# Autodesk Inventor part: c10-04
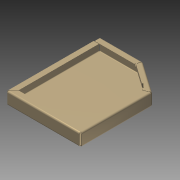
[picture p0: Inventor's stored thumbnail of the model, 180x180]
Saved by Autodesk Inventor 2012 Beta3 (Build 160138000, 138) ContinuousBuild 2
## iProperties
Created: 2011-01
Part Number: c10-04
Material: Aluminum-6061
Document SubType Name: Sheet Metal
Designer: Beta-8540w
Density: 2.71 g/cm^3
Sheet Metal Rule: Aluminum 3 mm
Author: Beta-8540w
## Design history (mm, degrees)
node "Face1"
  sketch "Sketch1"
    geometry: L1 (0, 0)-(240, 0); L2 (240, 0)-(240, 300); L3 (240, 300)-(0, 300); L4 (0, 300)-(0, 0); L5 (140, 300)-(240, 229.979)
    constraints: 10 end point, 2 parallel, 2 point on line, 1 horizontal, 1 perpendicular
    dimensions: "d0" = 240 distance of L3.end L2.end; "d1" = 300 distance of L2.end L1.end; "d2" = 35 deg angle of L3 L5; "d3" = 100 distance from line of L2 L5.start
node "Flange1"
node "Flange2"
node "Flange3"
body "Solid1"
face "Plate1" dims "Thickness" = 3 (derived)
sketch "Sketch2"
  geometry: L1 (0, 40)-(-300, 40); L2 (-300, 40)-(-300, 0); 2 other entities
  constraints: 4 end point, 4 other
face "Plate2" dims "d5" = 3 (= BendReliefWidth), "d6" = 1.5 (= BendReliefDepth), "d7" = 6 (= MinimumRemnant), "d8" = 2 (= BendRadius), "d9" = 40, "d10" = 90 deg, "d11" = 2 (= BendRadius), "d12" = 12 (= CornerReliefSize), "d13" = 1.5 (= GapSize), "d14" = 2 (= JacobiRadiusSize), "SeamGap" = 0.01, "Thickness" = 3 (derived)
bend "Bend1" dims "d5" = 3 (= BendReliefWidth), "d6" = 1.5 (= BendReliefDepth), "d7" = 6 (= MinimumRemnant), "d8" = 2 (= BendRadius), "d9" = 40, "d10" = 90 deg, "d11" = 2 (= BendRadius), "SeamGap" = 0.01, "Thickness" = 3 (derived)
feature "Corner1" dims "d9" = 40, "d10" = 90 deg, "d12" = 12 (= CornerReliefSize), "d13" = 1.5 (= GapSize), "d14" = 2 (= JacobiRadiusSize)
sketch "Sketch3"
  geometry: L1 (0, 20)-(-231.879, 20); L2 (-231.879, 20)-(-231.879, 0); 2 other entities
  constraints: 4 end point, 4 other
face "Plate3" dims "d15" = 3 (= BendReliefWidth), "d16" = 1.5 (= BendReliefDepth), "d17" = 6 (= MinimumRemnant), "d18" = 2 (= BendRadius), "d19" = 20, "d20" = 90 deg, "d21" = 2 (= BendRadius), "d22" = 12 (= CornerReliefSize), "d23" = 1.5 (= GapSize), "d24" = 2 (= JacobiRadiusSize), "d26" = 10, "SeamGap" = 0.01, "Thickness" = 3 (derived)
bend "Bend2" dims "d15" = 3 (= BendReliefWidth), "d16" = 1.5 (= BendReliefDepth), "d17" = 6 (= MinimumRemnant), "d18" = 2 (= BendRadius), "d19" = 20, "d20" = 90 deg, "d21" = 2 (= BendRadius), "SeamGap" = 0.01, "Thickness" = 3 (derived)
feature "Corner2" dims "d19" = 20, "d20" = 90 deg, "d22" = 12 (= CornerReliefSize), "d23" = 1.5 (= GapSize), "d24" = 2 (= JacobiRadiusSize)
sketch "Sketch4"
  geometry: L1 (-93.728, 0)-(-10, 0); L2 (-10, 0)-(-10, 15); L3 (-10, 15)-(-93.728, 15); L4 (-93.728, 15)-(-93.728, 0)
  constraints: 8 end point
face "Plate4" dims "d27" = 3 (= BendReliefWidth), "d28" = 1.5 (= BendReliefDepth), "d29" = 6 (= MinimumRemnant), "d30" = 2 (= BendRadius), "d31" = 10, "d32" = 10, "d33" = 15, "d34" = 90 deg, "d35" = 2 (= BendRadius), "d36" = 12 (= CornerReliefSize), "d37" = 1.5 (= GapSize), "d38" = 2 (= JacobiRadiusSize), "SeamGap" = 0.01, "Thickness" = 3 (derived)
bend "Bend3" dims "d27" = 3 (= BendReliefWidth), "d28" = 1.5 (= BendReliefDepth), "d29" = 6 (= MinimumRemnant), "d30" = 2 (= BendRadius), "d33" = 15, "d34" = 90 deg, "d35" = 2 (= BendRadius), "SeamGap" = 0.01, "Thickness" = 3 (derived)
feature "Corner3" dims "d33" = 15, "d34" = 90 deg, "d36" = 12 (= CornerReliefSize), "d37" = 1.5 (= GapSize), "d38" = 2 (= JacobiRadiusSize)
other parameters: "BendRadius" = 2 (derived), "BendReliefWidth" = 3 (= Thickness), "BendReliefDepth" = 1.5 (= 0.5 x Thickness), "CornerReliefSize" = 12 (= 4 x Thickness), "MinimumRemnant" = 6 (= 2 x Thickness), "TransitionRadius" = 2 (= BendRadius), "JacobiRadiusSize" = 2 (= BendRadius), "GapSize" = 1.5 (= 0.5 x Thickness), "d4" = 2 (= BendRadius)
